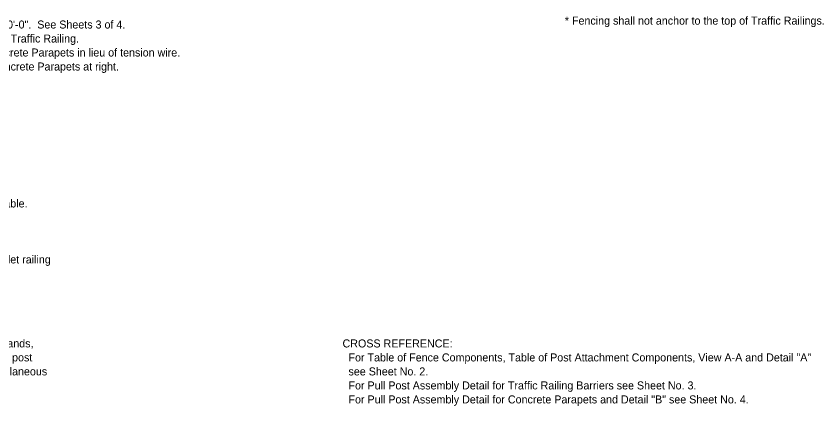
# Model space of a CAD drawing. Extents: x 0 to 41, y -96 to 25.
# Drawn here: x 16.13 to 36.47, y -95.62 to -85.82 of the extents above; entities that cross this region are included whole.
import ezdxf

# ---------------------------------------------------------------- set-up
doc = ezdxf.new("R2010")
doc.units = 0
doc.layers.add('Dimension', color=7, linetype='Continuous')

msp = doc.modelspace()

# ---------------------------------------------------------------- texts
at = {"layer": 'Dimension'}
for s, p in [('* Fencing shall not anchor to the top of Traffic Railings.', (29.947, -86.031)), ('  1.   A Pull Post Assembly is required at maximum intervals of 500\'-0".  See Sheets 3 of 4.', (8.106, -86.129)), ('  2.  Brace rails are only required for vertical fence installations on Traffic Railing.  ', (8.106, -86.481)), ('  3.  Provide horizontal rails for vertical fence installations on Concrete Parapets in lieu of tension wire.  ', (8.106, -86.833)), ('      Locate horizontal rails as shown in the Typical Section for Concrete Parapets at right.', (8.106, -87.185)), ('CROSS REFERENCE:', (24.348, -94.151)), ('  For Table of Fence Components, Table of Post Attachment Components, View A-A and Detail "A"', (24.348, -94.503)), ('  see Sheet No. 2.', (24.348, -94.855)), ('  For Pull Post Assembly Detail for Traffic Railing Barriers see Sheet No. 3.', (24.348, -95.207)), ('  For Pull Post Assembly Detail for Concrete Parapets and Detail "B" see Sheet No. 4.', (24.348, -95.559))]:
    msp.add_text(s, height=0.2016, dxfattribs=at).set_placement(p)
for s, p in [('  thickness of shim plates will be determined in the field.  Install chain link fence in accordance with ASTM F 567 as applicable.', (1.369, -90.63)), ('  See Index No. 521-820 - Pedestrian/Bicycle Railing for Concrete Parapet details.  Provide fencing in lieu of aluminum bullet railing ', (1.369, -92.038)), ('  Payment will be made under Fencing, Type R.  Payment includes posts, horizontal and expansion rails, brace rails and bands,', (1.369, -94.15)), ('  rail ends, combination rail ends, boulevard clamps, chain link fabric, tension wire, ties, hog rings, tension bars and bands, post', (1.369, -94.502)), ('  and loop caps, pipe clamps, base plates, anchor rods, bolts, nuts, washers, shim plates, spacers,  neoprene pads, miscellaneous', (1.369, -94.854))]:
    msp.add_text(s, height=0.2016, rotation=0, dxfattribs=at).set_placement(p)

doc.saveas('drawing.dxf')
